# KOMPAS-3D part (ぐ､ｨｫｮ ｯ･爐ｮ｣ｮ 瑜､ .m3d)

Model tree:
1. Эскиз:1
2. Операция выдавливания:1
     Расстояние 1 = 5
3. Фаска:1
     Угол = 45; Длина 1 = 1.5; Длина 2 = 1.5
4. Эскиз:2
5. Вырезать элемент выдавливания:1
     Расстояние 1 = 2.5
6. Эскиз:3
7. Операция выдавливания:2
     Расстояние 1 = 8
8. Скругление:1
     Радиус = 0.4
9. Фаска:2
     Угол = 45; Длина 1 = 0.25; Длина 2 = 0.25
10. Эскиз:4
11. Вырезать элемент выдавливания:2
     Расстояние 1 = 1.25
12. Фаска:4
     Угол = 45; Длина 1 = 1.25; Длина 2 = 1.25
13. Фаска:5
     Угол = 45; Длина 1 = 0.5; Длина 2 = 0.5
